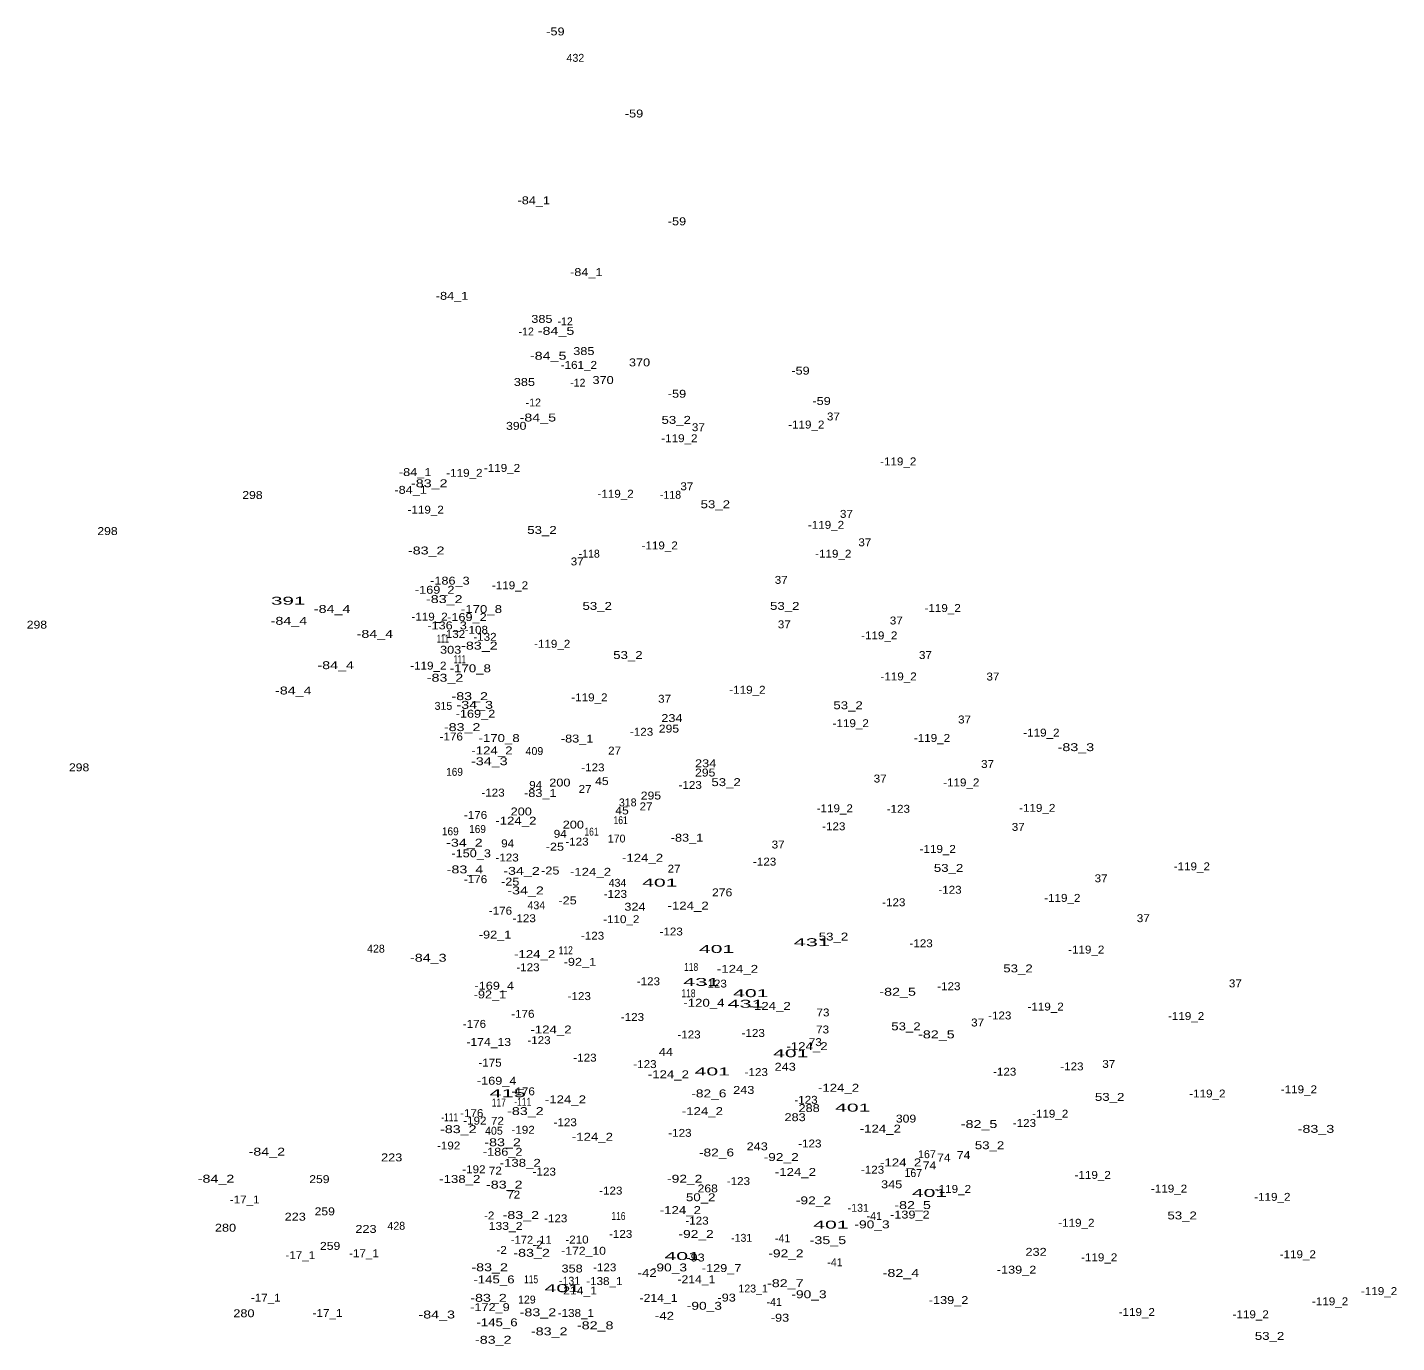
# Model space of a CAD drawing. Extents: x -658110 to -655750, y -1000429 to -997657.
# Drawn here: x -657514 to -656822, y -998322 to -997657 of the extents above; entities that cross this region are included whole.
import ezdxf
from ezdxf.enums import TextEntityAlignment as Align

# ---------------------------------------------------------------- set-up
doc = ezdxf.new("R2010")
doc.units = 0
doc.header["$LTSCALE"] = 1.6
doc.layers.add('24', color=7, linetype='Continuous')

msp = doc.modelspace()

# ---------------------------------------------------------------- texts
at = {"layer": '24'}
for s, width, p in [('-59', 1.2, (-657246.94, -997660.92)), ('-59', 1.2, (-657207.19, -997702.42)), ('-84_1', 1.2, (-657257.88, -997746.31)), ('-59', 1.2, (-657185.48, -997756.92)), ('-84_1', 1.2, (-657231.319, -997782.58)), ('-84_1', 1.2, (-657299.179, -997794.6)), ('385', 1.2, (-657253.76, -997806.27)), ('-84_5', 1.35, (-657246.6, -997812.3)), ('-84_5', 1.35, (-657250.58, -997824.9)), ('385', 1.2, (-657232.559, -997822.52)), ('-161_2', 1.1, (-657235.081, -997829.51)), ('370', 1.2, (-657204.41, -997828.24)), ('-59', 1.2, (-657123.05, -997832.42)), ('385', 1.2, (-657262.61, -997838.15)), ('370', 1.2, (-657222.83, -997837.16)), ('-59', 1.2, (-657185.48, -997844.1)), ('-59', 1.2, (-657112.39, -997847.76)), ('390', 1.15, (-657266.731, -997860.33)), ('-84_5', 1.35, (-657255.81, -997856.13)), ('53_2', 1.25, (-657185.86, -997857.31)), ('37', 1.1, (-657174.67, -997861.02)), ('-119_2', 1.1, (-657120.12, -997859.67)), ('37', 1.1, (-657106.42, -997855.59)), ('-119_2', 1.1, (-657184.25, -997866.59)), ('-119_2', 1.1, (-657273.921, -997881.59)), ('-119_2', 1.1, (-657073.65, -997878.31)), ('-84_1', 1.2, (-657317.84, -997883.72)), ('-83_2', 1.35, (-657310.699, -997889.35)), ('-119_2', 1.1, (-657292.931, -997884.09)), ('298', 1.15, (-657400.07, -997895.3)), ('-84_1', 1.2, (-657320.12, -997892.69)), ('-119_2', 1.1, (-657216.51, -997894.66)), ('37', 1.1, (-657180.48, -997890.88)), ('-119_2', 1.1, (-657312.51, -997902.71)), ('53_2', 1.25, (-657166.09, -997899.97)), ('-119_2', 1.1, (-657110.14, -997910.38)), ('37', 1.1, (-657099.83, -997904.84)), ('298', 1.15, (-657473.35, -997913.53)), ('53_2', 1.25, (-657253.72, -997912.97)), ('-83_2', 1.35, (-657312.23, -997923.35)), ('-119_2', 1.1, (-657194.231, -997920.78)), ('37', 1.1, (-657090.52, -997919.2)), ('37', 1.1, (-657235.93, -997928.89)), ('-119_2', 1.1, (-657106.49, -997924.98)), ('37', 1.1, (-657132.79, -997938.21)), ('-169_2', 1.2, (-657307.96, -997943.22)), ('-186_3', 1.2, (-657300.27, -997938.61)), ('-119_2', 1.1, (-657269.88, -997940.94)), ('391', 1.95, (-657382.023, -997948.75)), ('-83_2', 1.35, (-657303.12, -997947.93)), ('53_2', 1.25, (-657225.8, -997951.37)), ('53_2', 1.25, (-657131, -997951.37)), ('-84_4', 1.35, (-657381.62, -997958.91)), ('-84_4', 1.35, (-657359.8, -997952.9)), ('-119_2', 1.1, (-657310.541, -997956.79)), ('-169_2', 1.2, (-657291.66, -997957.01)), ('-170_8', 1.25, (-657284.321, -997952.96)), ('37', 1.1, (-657074.62, -997958.76)), ('-119_2', 1.1, (-657051.191, -997952.45)), ('298', 1.15, (-657509.02, -997960.85)), ('-84_4', 1.35, (-657338.19, -997965.52)), ('-136_3', 1.2, (-657301.701, -997961.23)), ('-132', 1.1, (-657298.421, -997965.55)), ('-108', 1.1, (-657286.91, -997963.45)), ('37', 1.1, (-657131.24, -997960.69)), ('-119_2', 1.1, (-657083.25, -997966.28)), ('111', 0.6, (-657303.81, -997967.9)), ('-83_2', 1.35, (-657285.36, -997971.45)), ('-132', 1.1, (-657282.541, -997967.01)), ('-119_2', 1.1, (-657248.571, -997970.52)), ('303', 1.2, (-657299.89, -997973.54)), ('111', 0.6, (-657295.28, -997978.32)), ('53_2', 1.25, (-657210.28, -997976.2)), ('37', 1.1, (-657059.89, -997976.21)), ('-84_4', 1.35, (-657358, -997981.34)), ('-119_2', 1.1, (-657311.171, -997981.57)), ('-170_8', 1.25, (-657289.951, -997982.92)), ('-119_2', 1.1, (-657073.461, -997987.02)), ('-83_2', 1.35, (-657302.73, -997987.69)), ('-119_2', 1.1, (-657149.87, -997993.76)), ('37', 1.1, (-657025.78, -997987.08)), ('-84_4', 1.35, (-657379.42, -997994.15)), ('-83_2', 1.35, (-657290.24, -997997)), ('-119_2', 1.1, (-657229.75, -997997.6)), ('37', 1.1, (-657191.73, -997998.32)), ('-169_2', 1.2, (-657287.34, -998005.88)), ('-34_3', 1.35, (-657287.7, -998001.4)), ('53_2', 1.25, (-657098.99, -998001.61)), ('-83_2', 1.35, (-657294.079, -998012.66)), ('295', 1.15, (-657189.53, -998013.41)), ('234', 1.2, (-657188.049, -998008.07)), ('-119_2', 1.1, (-657097.65, -998010.67)), ('37', 1.1, (-657040.12, -998008.8)), ('-176', 1.1, (-657299.579, -998017.4)), ('-170_8', 1.25, (-657275.4, -998018.18)), ('-83_1', 1.2, (-657235.959, -998018.44)), ('-123', 1.1, (-657203.39, -998015.01)), ('-119_2', 1.1, (-657056.571, -998018.14)), ('-119_2', 1.1, (-657001.27, -998015.45)), ('-124_2', 1.25, (-657279.02, -998024.43)), ('27', 1.1, (-657217.01, -998024.52)), ('-83_3', 1.35, (-656983.84, -998022.79)), ('298', 1.15, (-657487.69, -998032.99)), ('169', 0.95, (-657297.93, -998035.27)), ('-34_3', 1.35, (-657280.33, -998029.91)), ('-123', 1.1, (-657227.981, -998033.02)), ('234', 1.2, (-657170.99, -998030.96)), ('37', 1.1, (-657028.48, -998031.29)), ('94', 1.1, (-657256.91, -998041.87)), ('200', 1.2, (-657244.689, -998040.69)), ('45', 1.15, (-657223.429, -998039.96)), ('-123', 1.1, (-657178.811, -998041.91)), ('295', 1.15, (-657171.21, -998035.62)), ('53_2', 1.25, (-657160.65, -998040.48)), ('37', 1.1, (-657082.77, -998038.66)), ('-119_2', 1.1, (-657041.78, -998040.61)), ('-123', 1.1, (-657278.461, -998045.75)), ('-83_1', 1.2, (-657254.569, -998045.98)), ('27', 1.1, (-657231.94, -998043.91)), ('295', 1.15, (-657198.64, -998047.25)), ('200', 1.2, (-657264.199, -998055.3)), ('45', 1.15, (-657213.26, -998054.79)), ('27', 1.1, (-657201.11, -998052.74)), ('-119_2', 1.1, (-657105.711, -998053.69)), ('-123', 1.1, (-657073.591, -998053.96)), ('-119_2', 1.1, (-657003.38, -998053.48)), ('-176', 1.1, (-657287.299, -998057.07)), ('-124_2', 1.25, (-657266.919, -998059.97)), ('200', 1.2, (-657237.87, -998061.94)), ('161', 0.8, (-657213.951, -998059.69)), ('-123', 1.1, (-657106.24, -998062.8)), ('37', 1.1, (-657012.97, -998063.1)), ('169', 0.95, (-657300.06, -998065.33)), ('169', 0.95, (-657286.3, -998064.16)), ('94', 1.1, (-657244.5, -998066.59)), ('161', 0.8, (-657228.681, -998065.51)), ('-83_1', 1.2, (-657180.41, -998068.55)), ('-34_2', 1.35, (-657292.93, -998071.09)), ('-150_3', 1.2, (-657289.52, -998076.47)), ('94', 1.1, (-657271.06, -998071.44)), ('-25', 1.2, (-657247.2, -998073.13)), ('-123', 1.1, (-657236.03, -998070.53)), ('37', 1.1, (-657134.34, -998072.02)), ('-119_2', 1.1, (-657053.681, -998074.24)), ('-123', 1.1, (-657271.361, -998078.59)), ('-124_2', 1.25, (-657202.89, -998078.7)), ('-123', 1.1, (-657141.181, -998080.67)), ('53_2', 1.25, (-657048.19, -998083.84)), ('-119_2', 1.1, (-656925.231, -998083.06)), ('-83_4', 1.35, (-657292.65, -998084.6)), ('-176', 1.1, (-657287.299, -998089.53)), ('-25', 1.2, (-657269.78, -998090.78)), ('-34_2', 1.35, (-657264.05, -998085.34)), ('-25', 1.2, (-657249.52, -998085.16)), ('-124_2', 1.25, (-657229.189, -998085.81)), ('27', 1.1, (-657186.96, -998084.25)), ('37', 1.1, (-656971.1, -998089.09)), ('-34_2', 1.35, (-657262.01, -998095.23)), ('-123', 1.1, (-657216.64, -998096.99)), ('401', 2, (-657194.159, -998091.29)), ('276', 1.15, (-657162.65, -998096.2)), ('-123', 1.1, (-657047.481, -998094.88)), ('-25', 1.2, (-657240.8, -998100.28)), ('324', 1.2, (-657206.73, -998103.45)), ('-124_2', 1.25, (-657179.85, -998102.9)), ('-123', 1.1, (-657075.9, -998101.21)), ('-119_2', 1.1, (-656990.711, -998099)), ('-176', 1.1, (-657274.72, -998105.47)), ('-123', 1.1, (-657262.721, -998109.29)), ('-110_2', 1.1, (-657213.64, -998109.77)), ('37', 1.1, (-656949.77, -998109.26)), ('-92_1', 1.2, (-657277.431, -998117.55)), ('-123', 1.1, (-657228.16, -998118.12)), ('-123', 1.1, (-657188.421, -998116)), ('53_2', 1.25, (-657106.37, -998118.55)), ('112', 0.8, (-657241.71, -998125.46)), ('401', 2, (-657165.479, -998124.83)), ('431', 2.05, (-657117.303, -998121.4)), ('-123', 1.1, (-657062.081, -998121.95)), ('-119_2', 1.1, (-656978.611, -998125.13)), ('-84_3', 1.35, (-657311.19, -998129.27)), ('-124_2', 1.25, (-657257.419, -998127.4)), ('-92_1', 1.2, (-657234.541, -998131.32)), ('-123', 1.1, (-657260.801, -998134.06)), ('118', 0.8, (-657178.32, -998133.94)), ('-124_2', 1.25, (-657154.89, -998134.88)), ('53_2', 1.25, (-657013.1, -998134.65)), ('-169_4', 1.2, (-657277.85, -998143.4)), ('-123', 1.1, (-657199.941, -998141.17)), ('431', 2.05, (-657173.213, -998141.49)), ('-123', 1.1, (-657166.14, -998142.32)), ('-123', 1.1, (-657048.061, -998143.66)), ('37', 1.1, (-656903.24, -998142.22)), ('-92_1', 1.2, (-657280.02, -998147.8)), ('-123', 1.1, (-657234.88, -998148.66)), ('118', 0.8, (-657179.67, -998147.23)), ('-120_4', 1.25, (-657171.87, -998152.02)), ('431', 2.05, (-657150.833, -998152.51)), ('401', 2, (-657148.169, -998147.16)), ('-82_5', 1.35, (-657073.939, -998146.47)), ('-176', 1.1, (-657263.39, -998157.61)), ('-123', 1.1, (-657208, -998159.22)), ('-124_2', 1.25, (-657138.38, -998153.61)), ('73', 1.1, (-657111.69, -998156.92)), ('-123', 1.1, (-657022.331, -998158.45)), ('-119_2', 1.1, (-656999.14, -998153.96)), ('-119_2', 1.1, (-656928.12, -998158.73)), ('-176', 1.1, (-657287.87, -998162.7)), ('-124_2', 1.25, (-657249.16, -998165.53)), ('73', 1.1, (-657111.88, -998165.53)), ('53_2', 1.25, (-657069.73, -998163.93)), ('37', 1.1, (-657033.51, -998162)), ('-174_13', 1.15, (-657280.66, -998171.85)), ('-123', 1.1, (-657255.231, -998170.94)), ('-123', 1.1, (-657179.39, -998168.06)), ('-123', 1.1, (-657146.941, -998167.29)), ('73', 1.1, (-657115.55, -998171.92)), ('-82_5', 1.35, (-657054.36, -998168)), ('-123', 1.1, (-657232, -998179.77)), ('44', 1.2, (-657191.09, -998176.88)), ('401', 2, (-657127.959, -998177.55)), ('-124_2', 1.25, (-657119.75, -998173.97)), ('-175', 1.1, (-657279.99, -998182.31)), ('-123', 1.1, (-657201.671, -998183.04)), ('401', 2, (-657167.649, -998186.75)), ('-123', 1.1, (-657145.41, -998187.07)), ('243', 1.2, (-657130.78, -998184.37)), ('-123', 1.1, (-657019.841, -998186.88)), ('-123', 1.1, (-656985.861, -998184.19)), ('37', 1.1, (-656967.22, -998182.95)), ('-169_4', 1.2, (-657276.63, -998191.44)), ('-124_2', 1.25, (-657189.829, -998188.19)), ('415', 2.05, (-657271.063, -998197.75)), ('-176', 1.1, (-657263.209, -998196.78)), ('-124_2', 1.25, (-657241.86, -998200.87)), ('-82_6', 1.3, (-657169.37, -998197.85)), ('243', 1.2, (-657151.72, -998196.1)), ('-123', 1.1, (-657120.26, -998201.09)), ('-124_2', 1.25, (-657103.809, -998195)), ('53_2', 1.25, (-656966.76, -998199.62)), ('-119_2', 1.1, (-656917.37, -998197.91)), ('-119_2', 1.1, (-656871.101, -998195.8)), ('-176', 1.1, (-657289.23, -998207.82)), ('117', 0.8, (-657275.541, -998202.49)), ('-83_2', 1.35, (-657262.12, -998206.79)), ('-111', 0.8, (-657263.421, -998202.07)), ('-124_2', 1.25, (-657172.64, -998206.81)), ('288', 1.2, (-657118.689, -998205.28)), ('401', 2, (-657096.639, -998205.04)), ('-119_2', 1.1, (-656996.841, -998208.12)), ('-111', 0.8, (-657300.38, -998209.95)), ('-192', 1.1, (-657287.65, -998211.62)), ('72', 1.1, (-657276.23, -998211.71)), ('-123', 1.1, (-657241.99, -998212.43)), ('283', 1.2, (-657125.77, -998209.88)), ('309', 1.15, (-657069.701, -998210.59)), ('-82_5', 1.35, (-657032.79, -998213.34)), ('-123', 1.1, (-657009.861, -998212.81)), ('-83_2', 1.35, (-657296.01, -998215.93)), ('-192', 1.1, (-657263.27, -998216.23)), ('-124_2', 1.25, (-657228.23, -998219.78)), ('-123', 1.1, (-657184, -998217.8)), ('-124_2', 1.25, (-657082.689, -998215.65)), ('-83_3', 1.35, (-656862.48, -998215.78)), ('-84_2', 1.35, (-657392.81, -998227.31)), ('-192', 1.1, (-657300.9, -998224.2)), ('-186_2', 1.2, (-657273.591, -998227.35)), ('-83_2', 1.35, (-657273.64, -998222.55)), ('-82_6', 1.3, (-657165.5, -998227.72)), ('243', 1.2, (-657144.929, -998224.61)), ('-123', 1.1, (-657118.341, -998223.18)), ('74', 1.15, (-657040.6, -998229.05)), ('53_2', 1.25, (-657027.47, -998224.05)), ('223', 1.2, (-657329.699, -998230.21)), ('-192', 1.1, (-657288.13, -998236.21)), ('-138_2', 1.25, (-657264.73, -998232.95)), ('-92_2', 1.3, (-657132.81, -998230.03)), ('-124_2', 1.25, (-657072.419, -998232.75)), ('74', 1.15, (-657057.81, -998234.27)), ('74', 1.15, (-657050.56, -998230.3)), ('-84_2', 1.35, (-657418.49, -998240.99)), ('259', 1.15, (-657366.24, -998241.2)), ('-138_2', 1.25, (-657295.26, -998241.12)), ('72', 1.1, (-657277.3, -998236.91)), ('-123', 1.1, (-657252.551, -998237.4)), ('-92_2', 1.3, (-657181.58, -998240.99)), ('-123', 1.1, (-657154.431, -998242.2)), ('-124_2', 1.25, (-657125.6, -998237.55)), ('-123', 1.1, (-657086.65, -998236.44)), ('-119_2', 1.1, (-656975.341, -998239.05)), ('-83_2', 1.35, (-657272.78, -998243.97)), ('72', 1.1, (-657268.02, -998249)), ('-123', 1.1, (-657218.951, -998247)), ('268', 1.15, (-657169.93, -998245.88)), ('345', 1.2, (-657076.97, -998243.8)), ('401', 2, (-657057.839, -998248.17)), ('-119_2', 1.1, (-657046, -998246.15)), ('-119_2', 1.1, (-656936.74, -998245.96)), ('-17_1', 1.1, (-657404, -998251.5)), ('-124_2', 1.25, (-657183.78, -998256.85)), ('50_2', 1.25, (-657173.49, -998250.36)), ('-92_2', 1.3, (-657116.49, -998251.93)), ('-82_5', 1.35, (-657066.38, -998254.31)), ('-119_2', 1.1, (-656884.541, -998250.16)), ('223', 1.2, (-657378.459, -998260.18)), ('259', 1.15, (-657363.53, -998257.49)), ('-2', 1.1, (-657280.41, -998259.56)), ('-83_2', 1.35, (-657264.419, -998259.33)), ('-123', 1.1, (-657246.791, -998261.03)), ('116', 0.8, (-657215.071, -998259.86)), ('-123', 1.1, (-657175.361, -998262.18)), ('-139_2', 1.2, (-657067.78, -998259.11)), ('-119_2', 1.1, (-656983.591, -998263.25)), ('53_2', 1.25, (-656930.13, -998259.56)), ('280', 1.2, (-657413.699, -998265.76)), ('223', 1.2, (-657342.689, -998266.38)), ('133_2', 1.15, (-657272.11, -998264.87)), ('-123', 1.1, (-657213.961, -998268.9)), ('-92_2', 1.3, (-657175.82, -998268.93)), ('401', 2, (-657107.679, -998264.21)), ('-90_3', 1.3, (-657086.89, -998264.07)), ('259', 1.15, (-657360.81, -998274.94)), ('-2', 1.1, (-657274.11, -998277.01)), ('-172_11', 1.05, (-657259.12, -998271.85)), ('-2', 1.1, (-657255.98, -998274.3)), ('-172_10', 1.15, (-657232.681, -998277.4)), ('-210', 1.1, (-657236.03, -998271.74)), ('-35_5', 1.35, (-657109.189, -998272.05)), ('-17_1', 1.1, (-657375.89, -998279.62)), ('-17_1', 1.1, (-657343.711, -998278.65)), ('-83_2', 1.35, (-657258.949, -998278.45)), ('401', 2, (-657182.859, -998280.09)), ('-93', 1.2, (-657176.12, -998280.82)), ('-92_2', 1.3, (-657130.41, -998278.72)), ('232', 1.2, (-657003.949, -998277.96)), ('-119_2', 1.1, (-656972.071, -998280.72)), ('-119_2', 1.1, (-656871.671, -998279.16)), ('-83_2', 1.35, (-657280.169, -998285.75)), ('358', 1.2, (-657238.49, -998286.38)), ('-123', 1.1, (-657222.02, -998285.8)), ('-42', 1.25, (-657200.58, -998288.63)), ('-90_3', 1.3, (-657189.3, -998285.84)), ('-129_7', 1.2, (-657162.93, -998286.16)), ('-82_4', 1.35, (-657072.27, -998288.62)), ('-139_2', 1.2, (-657013.831, -998286.97)), ('-145_6', 1.25, (-657278, -998291.89)), ('115', 0.8, (-657259.23, -998291.82)), ('401', 2, (-657243.489, -998296.34)), ('-214_1', 1.15, (-657235.459, -998297.48)), ('-138_1', 1.1, (-657222.199, -998292.74)), ('-214_1', 1.15, (-657175.65, -998291.81)), ('-82_7', 1.35, (-657130.72, -998293.81)), ('-119_2', 1.1, (-656830.581, -998297.79)), ('-17_1', 1.1, (-657393.341, -998301.14)), ('-83_2', 1.35, (-657280.74, -998301.21)), ('-214_1', 1.15, (-657194.799, -998301.24)), ('-90_3', 1.3, (-657171.64, -998305.24)), ('-93', 1.2, (-657160.38, -998301.08)), ('-90_3', 1.3, (-657118.77, -998299.41)), ('-139_2', 1.2, (-657048.201, -998302.33)), ('-119_2', 1.1, (-656855.351, -998302.98)), ('280', 1.2, (-657404.39, -998309.01)), ('-17_1', 1.1, (-657362.13, -998308.9)), ('-84_3', 1.35, (-657306.92, -998309.64)), ('-172_9', 1.2, (-657280.02, -998305.91)), ('-83_2', 1.35, (-657255.78, -998308.51)), ('-138_1', 1.1, (-657236.6, -998308.87)), ('-42', 1.25, (-657191.81, -998310.29)), ('-93', 1.2, (-657133.4, -998311.26)), ('-119_2', 1.1, (-656953.061, -998308.38)), ('-119_2', 1.1, (-656895.471, -998309.54)), ('-145_6', 1.25, (-657276.46, -998313.59)), ('-83_2', 1.35, (-657250.069, -998318.16)), ('-82_8', 1.35, (-657226.819, -998315.1)), ('-83_2', 1.35, (-657278.34, -998322.43)), ('53_2', 1.25, (-656885.93, -998320.46))]:
    msp.add_text(s, height=4, dxfattribs=dict(at, width=width)).set_placement(p, align=Align.CENTER)
for s, p in [('432', (-657236.841, -997674.26)), ('-12', (-657261.691, -997812.64)), ('-12', (-657242.01, -997807.5)), ('-12', (-657235.62, -997838.53)), ('-12', (-657258.101, -997848.52)), ('-118', (-657188.75, -997895.19)), ('-118', (-657229.841, -997924.97)), ('315', (-657303.53, -998001.91)), ('409', (-657257.551, -998024.77)), ('318', (-657210.38, -998050.72)), ('170', (-657215.981, -998069)), ('434', (-657215.526, -998091.39)), ('434', (-657256.576, -998102.75)), ('428', (-657337.651, -998124.66)), ('405', (-657278.005, -998216.71)), ('167', (-657059.13, -998228.59)), ('167', (-657066.02, -998238.1)), ('-131', (-657093.841, -998255.7)), ('-41', (-657085.74, -998259.85)), ('428', (-657327.361, -998264.79)), ('-131', (-657152.791, -998270.87)), ('-41', (-657132.08, -998271.09)), ('-41', (-657105.62, -998283.22)), ('-131', (-657239.77, -998292.58)), ('123_1', (-657146.98, -998296.5)), ('129', (-657261.361, -998302.08)), ('-41', (-657136.34, -998303.29))]:
    msp.add_text(s, height=4, dxfattribs=at).set_placement(p, align=Align.CENTER)

doc.saveas('drawing.dxf')
